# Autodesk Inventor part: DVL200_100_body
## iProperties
Created: 2009-09
Part Number: DVL200_100_body
Document SubType Name: Modeling
Designer: TB
Mass: 7118.17 g
Surface Area: 6213.3 cm^2
Volume: 7118.17 cm^3
Density: 1 g/cm^3
Author: TB
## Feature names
1. Kropp [Revolution]
2. Chamfer
3. Extrusion2
4. Hole1
5. Revolution2
6. Hole2
7. Fillet1
